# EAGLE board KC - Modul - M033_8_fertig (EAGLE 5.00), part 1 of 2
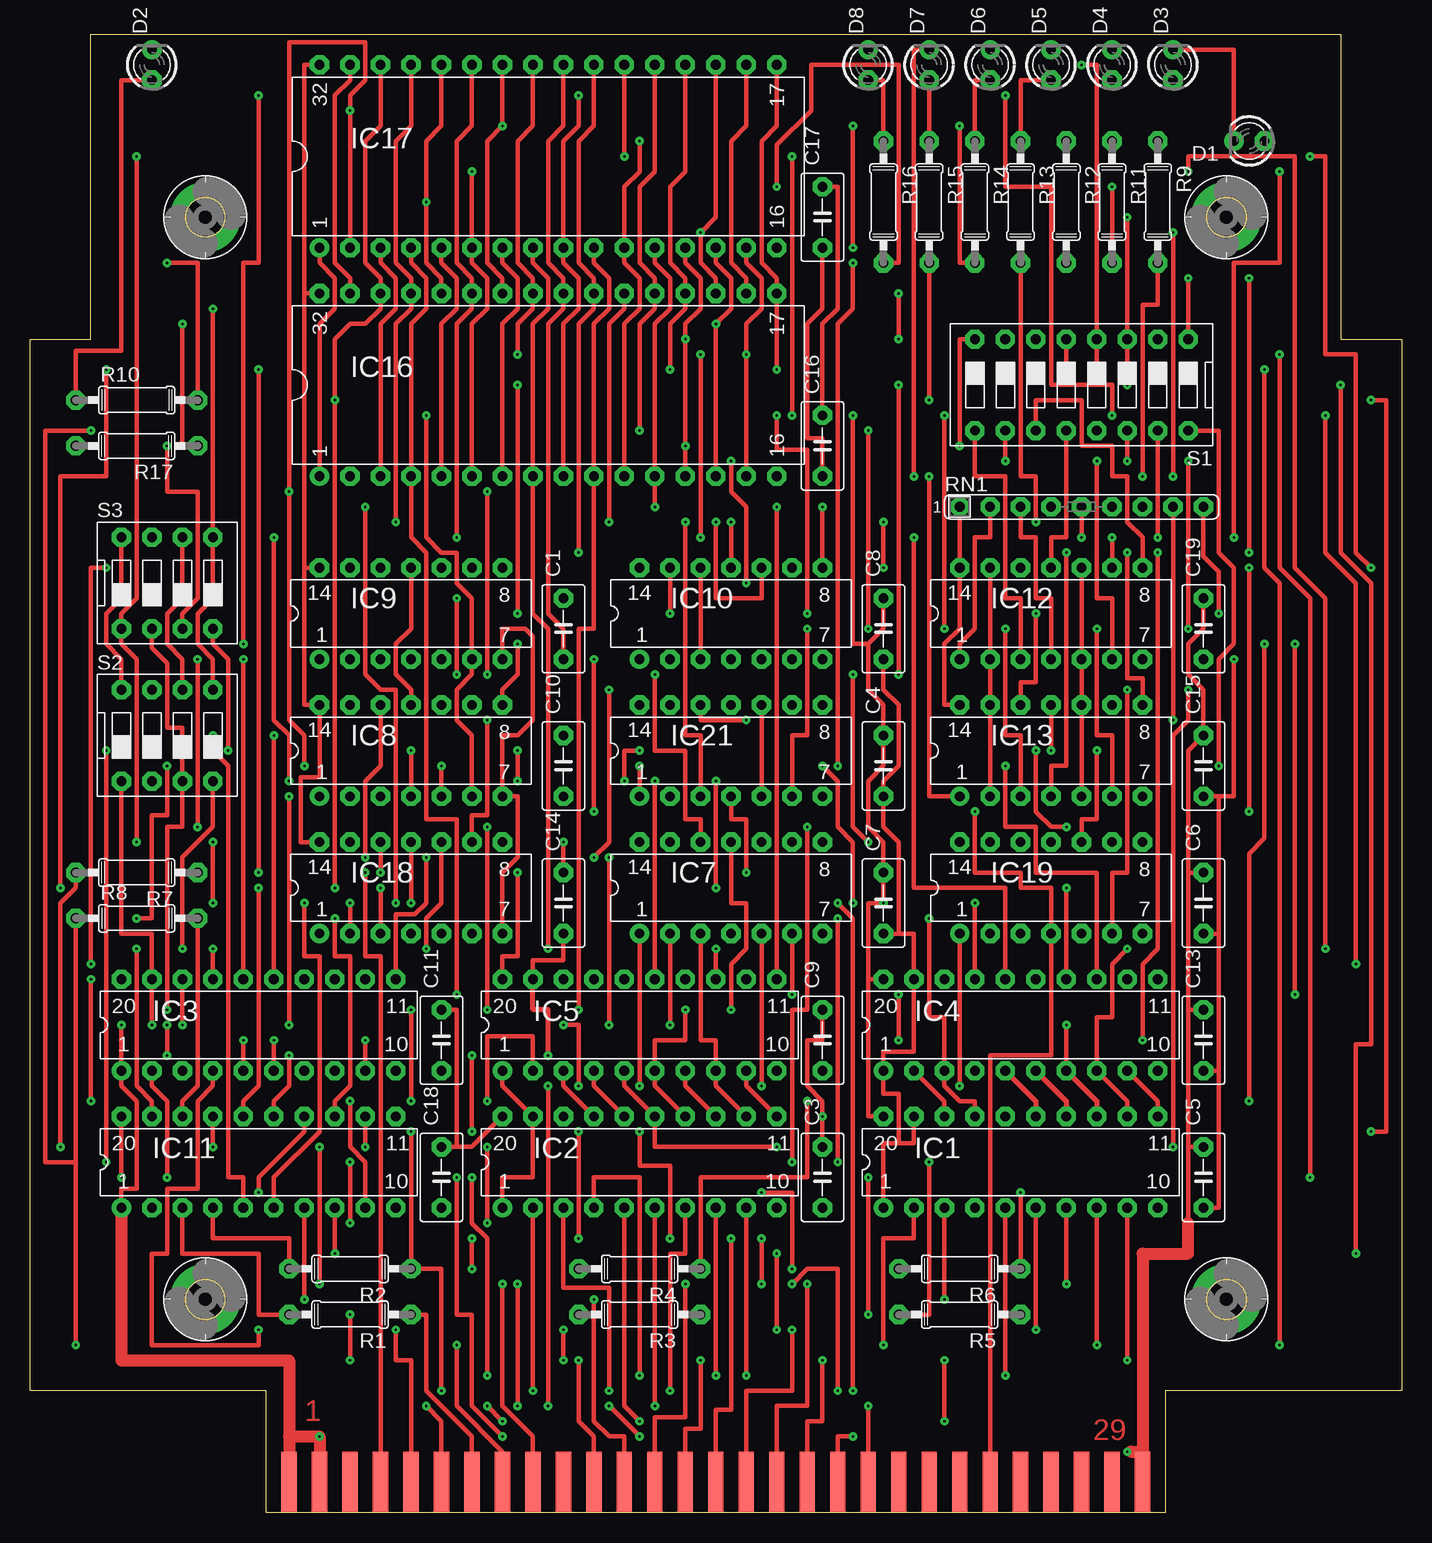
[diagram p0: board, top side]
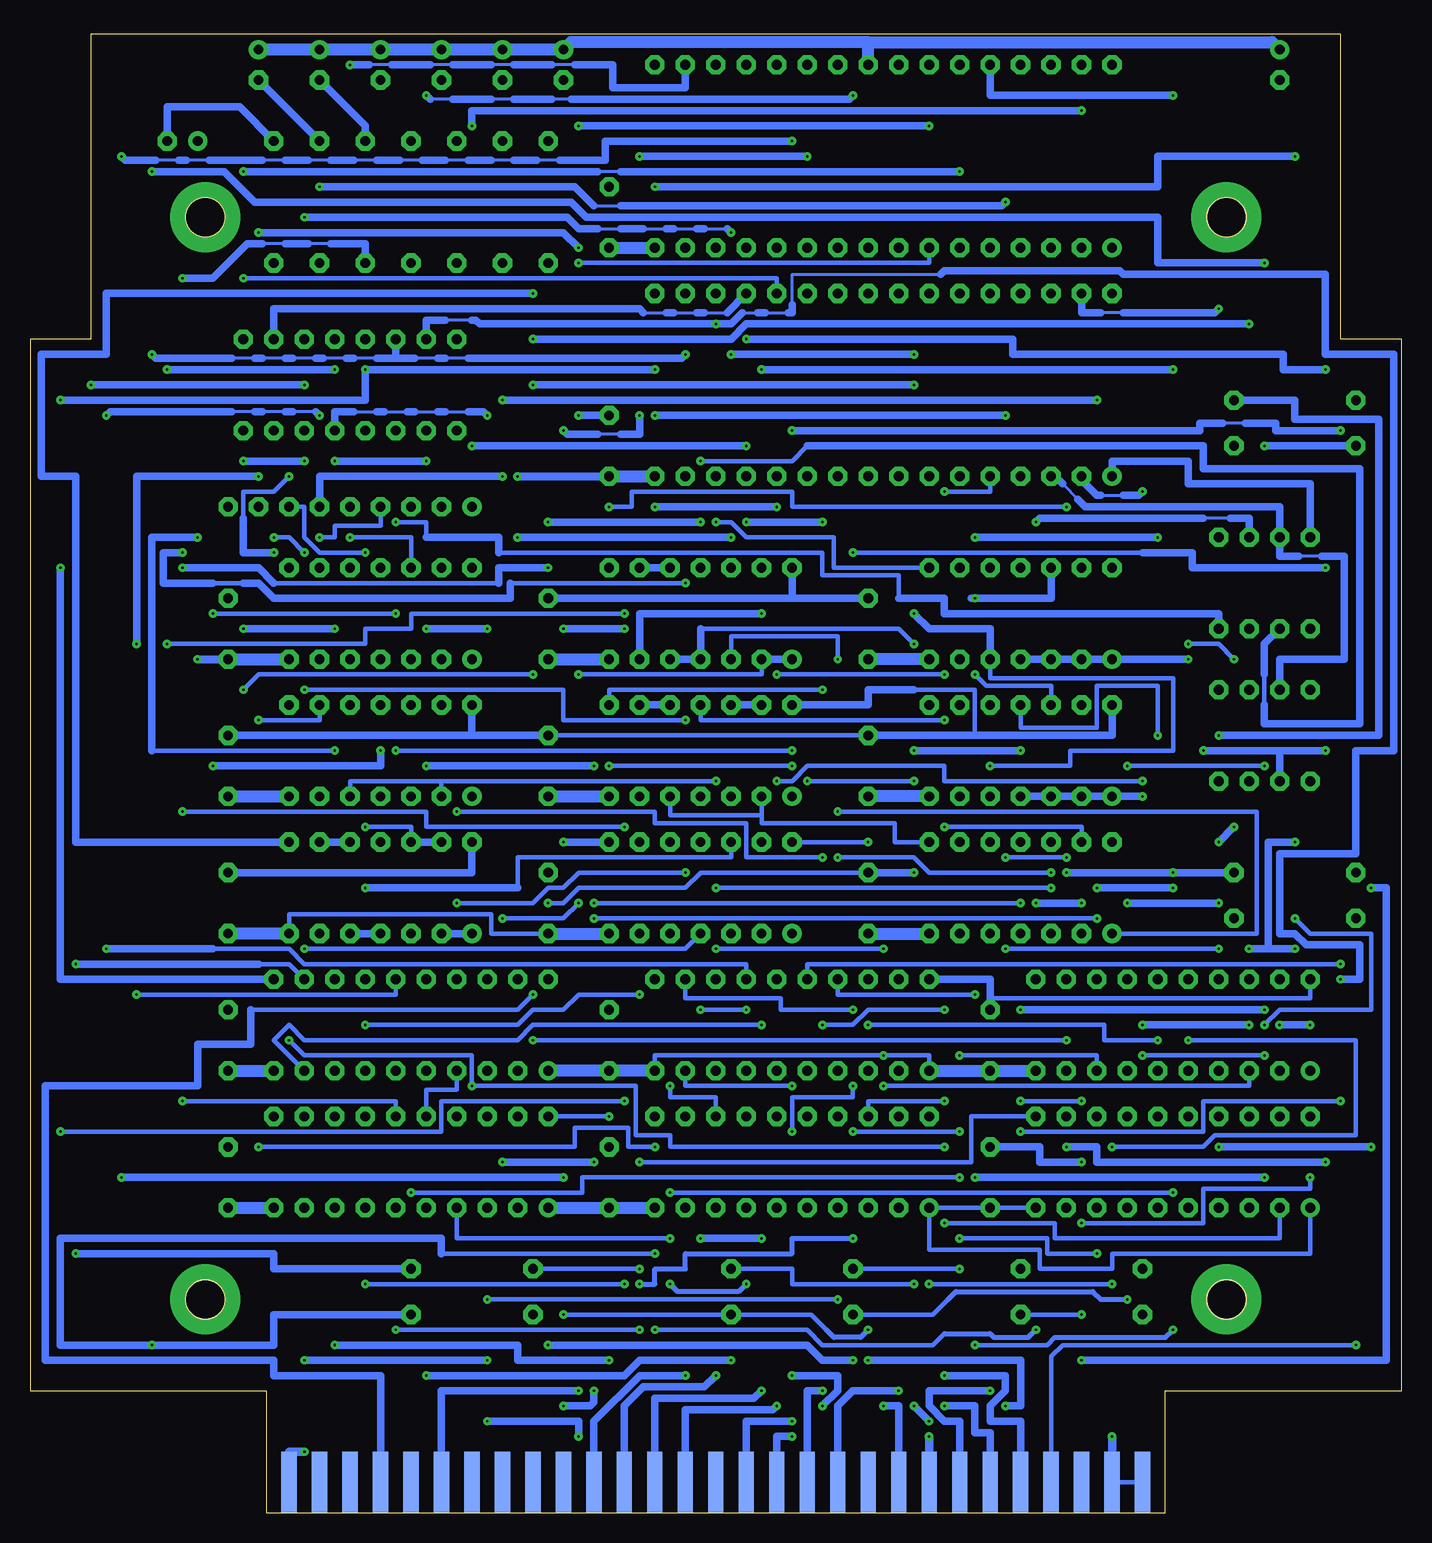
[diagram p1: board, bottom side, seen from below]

Size 114.3 x 123.19 mm. Coordinates in mm from the lower left corner, seen from the top.
Outline: 114.3,97.79 114.3,10.16 94.62,10.16 94.62,0 19.69,0 19.69,10.16 0,10.16 0,97.79 5.08,97.79 5.08,123.19 109.22,123.19 109.22,97.79 114.3,97.79
Copper layers (1*16): Top 0.035mm / dielectric 1.5mm / Bottom 0.035mm
Design rules "default": minimum track width 10mil, minimum drill 24mil, track to track 8mil, track to pad 8mil, pad to pad 8mil, via to via 8mil, smd to smd 8mil, copper to edge 40mil, drill to drill 8mil, minimum pad ring 10mil, minimum via ring 8mil, stop-mask expansion 4mil, vias tented up to drill 0mil, thermal gap 10mil
Holes 3.2 mm at 14.61,107.95 99.69,107.95 99.69,17.78 14.61,17.78

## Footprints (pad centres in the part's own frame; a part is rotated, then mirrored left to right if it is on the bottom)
C5B3,5 = drill 0.813 pad 1.6 octagon: 1 -2.54,0; 2 2.54,0
LED3 = drill 0.813 pad 1.6 octagon: A -1.27,0 | drill 0.813 pad 1.6 round: K 1.27,0
DIL20 = drill 0.813 pad 1.6 round: 1 -11.43,-3.81 | drill 0.813 pad 1.6 octagon: 2 -8.89,-3.81; 3 -6.35,-3.81; 4 -3.81,-3.81; 5 -1.27,-3.81; 6 1.27,-3.81; 7 3.81,-3.81; 8 6.35,-3.81; 9 8.89,-3.81; 10 11.43,-3.81; 11 11.43,3.81; 12 8.89,3.81; 13 6.35,3.81; 14 3.81,3.81; 15 1.27,3.81; 16 -1.27,3.81; 17 -3.81,3.81; 18 -6.35,3.81; 19 -8.89,3.81; 20 -11.43,3.81
DIL14 = drill 0.813 pad 1.6 round: 1 -7.62,-3.81 | drill 0.813 pad 1.6 octagon: 2 -5.08,-3.81; 3 -2.54,-3.81; 4 0,-3.81; 5 2.54,-3.81; 6 5.08,-3.81; 7 7.62,-3.81; 8 7.62,3.81; 9 5.08,3.81; 10 2.54,3.81; 11 0,3.81; 12 -2.54,3.81; 13 -5.08,3.81; 14 -7.62,3.81
DIL32 = drill 0.813 pad 1.6 round: 1 -19.05,-7.62 | drill 0.813 pad 1.6 octagon: 2 -16.51,-7.62; 3 -13.97,-7.62; 4 -11.43,-7.62; 5 -8.89,-7.62; 6 -6.35,-7.62; 7 -3.81,-7.62; 8 -1.27,-7.62; 9 1.27,-7.62; 10 3.81,-7.62; 11 6.35,-7.62; 12 8.89,-7.62; 13 11.43,-7.62; 14 13.97,-7.62; 15 16.51,-7.62; 16 19.05,-7.62; 17 19.05,7.62; 18 16.51,7.62; 19 13.97,7.62; 20 11.43,7.62; 21 8.89,7.62; 22 6.35,7.62; 23 3.81,7.62; 24 1.27,7.62; 25 -1.27,7.62; 26 -3.81,7.62; 27 -6.35,7.62; 28 -8.89,7.62; 29 -11.43,7.62; 30 -13.97,7.62; 31 -16.51,7.62; 32 -19.05,7.62
BO3,0-P = drill 3.023 pad 5.842 round: B3,0 0,0
SMD2 = smd 1.27 x 2.54: 1 0,0
0207/10 = drill 0.813 pad 1.6 octagon: 1 -5.08,0; 2 5.08,0
SIL9 = drill 0.813 pad 1.6 round: 1 -10.16,0 | drill 0.813 pad 1.6 octagon: 2 -7.62,0; 3 -5.08,0; 4 -2.54,0; 5 0,0; 6 2.54,0; 7 5.08,0; 8 7.62,0; 9 10.16,0
DS-08 = drill 0.813 pad 1.6 octagon: 1 -8.89,-3.81; 2 -6.35,-3.81; 3 -3.81,-3.81; 4 -1.27,-3.81; 5 1.27,-3.81; 6 3.81,-3.81; 7 6.35,-3.81; 8 8.89,-3.81; 9 8.89,3.81; 10 6.35,3.81; 11 3.81,3.81; 12 1.27,3.81; 13 -1.27,3.81; 14 -3.81,3.81; 15 -6.35,3.81; 16 -8.89,3.81
DS-04 = drill 0.813 pad 1.6 octagon: 1 -3.81,-3.81; 2 -1.27,-3.81; 3 1.27,-3.81; 4 3.81,-3.81; 5 3.81,3.81; 6 1.27,3.81; 7 -1.27,3.81; 8 -3.81,3.81

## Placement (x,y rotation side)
C1  C5B3,5  [C5B3,5]  44.45,73.66 90 top
C3  C5B3,5  [C5B3,5]  66.04,27.94 90 top
C4  C5B3,5  [C5B3,5]  71.12,62.23 90 top
C5  C5B3,5  [C5B3,5]  97.79,27.94 90 top
C6  C5B3,5  [C5B3,5]  97.79,50.8 90 top
C7  C5B3,5  [C5B3,5]  71.12,50.8 90 top
C8  C5B3,5  [C5B3,5]  71.12,73.66 90 top
C9  C5B3,5  [C5B3,5]  66.04,39.37 90 top
C10  C5B3,5  [C5B3,5]  44.45,62.23 90 top
C11  C5B3,5  [C5B3,5]  34.29,39.37 90 top
C13  C5B3,5  [C5B3,5]  97.79,39.37 90 top
C14  C5B3,5  [C5B3,5]  44.45,50.8 90 top
C15  C5B3,5  [C5B3,5]  97.79,62.23 90 top
C16  C5B3,5  [C5B3,5]  66.04,88.9 90 top
C17  C5B3,5  [C5B3,5]  66.04,107.95 90 top
C18  C5B3,5  [C5B3,5]  34.29,27.94 90 top
C19  C5B3,5  [C5B3,5]  97.79,73.66 90 top
D1  [LED3]  101.6,114.3 180 top
D2  [LED3]  10.16,120.65 90 top
D3  [LED3]  95.25,120.65 90 top
D4  [LED3]  90.17,120.65 90 top
D5  [LED3]  85.09,120.65 90 top
D6  [LED3]  80.01,120.65 90 top
D7  [LED3]  74.93,120.65 90 top
D8  [LED3]  69.85,120.65 90 top
IC1  74540  [DIL20]  82.55,29.21 0 top
IC2  74540  [DIL20]  50.8,29.21 0 top
IC3  74540  [DIL20]  19.05,40.64 0 top
IC4  74540  [DIL20]  82.55,40.64 0 top
IC5  74540  [DIL20]  50.8,40.64 0 top
IC7  7430  [DIL14]  58.42,52.07 0 top
IC8  7430  [DIL14]  31.75,63.5 0 top
IC9  7430  [DIL14]  31.75,74.93 0 top
IC10  7400  [DIL14]  58.42,74.93 0 top
IC11  74374  [DIL20]  19.05,29.21 0 top
IC12  7403  [DIL14]  85.09,74.93 0 top
IC13  7403  [DIL14]  85.09,63.5 0 top
IC16  628128P  [DIL32]  43.18,93.98 0 top
IC17  628128P  [DIL32]  43.18,113.03 0 top
IC18  7408  [DIL14]  31.75,52.07 0 top
IC19  7420  [DIL14]  85.09,52.07 0 top
IC21  7400  [DIL14]  58.42,63.5 0 top
PAD1  BO3,0P  [BO3,0-P]  99.69,17.78 0 top
PAD2  BO3,0P  [BO3,0-P]  14.61,17.78 0 top
PAD3  BO3,0P  [BO3,0-P]  99.69,107.95 0 top
PAD4  BO3,0P  [BO3,0-P]  14.61,107.95 0 top
PAD5  SMD2  [SMD2]  21.59,1.27 0 top
PAD6  SMD2  [SMD2]  24.13,1.27 0 top
PAD7  SMD2  [SMD2]  26.67,1.27 0 top
PAD8  SMD2  [SMD2]  29.21,1.27 0 top
PAD9  SMD2  [SMD2]  31.75,1.27 0 top
PAD10  SMD2  [SMD2]  34.29,1.27 0 top
PAD11  SMD2  [SMD2]  36.83,1.27 0 top
PAD12  SMD2  [SMD2]  39.37,1.27 0 top
PAD13  SMD2  [SMD2]  41.91,1.27 0 top
PAD14  SMD2  [SMD2]  44.45,1.27 0 top
PAD15  SMD2  [SMD2]  46.99,1.27 0 top
PAD16  SMD2  [SMD2]  49.53,1.27 0 top
PAD17  SMD2  [SMD2]  52.07,1.27 0 top
PAD18  SMD2  [SMD2]  54.61,1.27 0 top
PAD19  SMD2  [SMD2]  57.15,1.27 0 top
PAD20  SMD2  [SMD2]  59.69,1.27 0 top
PAD21  SMD2  [SMD2]  62.23,1.27 0 top
PAD22  SMD2  [SMD2]  64.77,1.27 0 top
PAD23  SMD2  [SMD2]  67.31,1.27 0 top
PAD24  SMD2  [SMD2]  69.85,1.27 0 top
PAD25  SMD2  [SMD2]  72.39,1.27 0 top
PAD26  SMD2  [SMD2]  74.93,1.27 0 top
PAD27  SMD2  [SMD2]  77.47,1.27 0 top
PAD28  SMD2  [SMD2]  80.01,1.27 0 top
PAD29  SMD2  [SMD2]  82.55,1.27 0 top
PAD30  SMD2  [SMD2]  85.09,1.27 0 top
PAD31  SMD2  [SMD2]  87.63,1.27 0 top
PAD32  SMD2  [SMD2]  90.17,1.27 0 top
PAD33  SMD2  [SMD2]  92.71,1.27 0 top
PAD34  SMD2  [SMD2]  21.59,3.81 0 top
PAD35  SMD2  [SMD2]  24.13,3.81 0 top
PAD36  SMD2  [SMD2]  26.67,3.81 0 top
PAD37  SMD2  [SMD2]  29.21,3.81 0 top
PAD38  SMD2  [SMD2]  31.75,3.81 0 top
PAD39  SMD2  [SMD2]  34.29,3.81 0 top
PAD40  SMD2  [SMD2]  36.83,3.81 0 top
PAD41  SMD2  [SMD2]  39.37,3.81 0 top
PAD42  SMD2  [SMD2]  41.91,3.81 0 top
PAD43  SMD2  [SMD2]  44.45,3.81 0 top
PAD44  SMD2  [SMD2]  46.99,3.81 0 top
PAD45  SMD2  [SMD2]  49.53,3.81 0 top
PAD46  SMD2  [SMD2]  52.07,3.81 0 top
PAD47  SMD2  [SMD2]  54.61,3.81 0 top
PAD48  SMD2  [SMD2]  57.15,3.81 0 top
PAD49  SMD2  [SMD2]  59.69,3.81 0 top
PAD50  SMD2  [SMD2]  62.23,3.81 0 top
PAD51  SMD2  [SMD2]  64.77,3.81 0 top
PAD52  SMD2  [SMD2]  67.31,3.81 0 top
PAD53  SMD2  [SMD2]  69.85,3.81 0 top
PAD54  SMD2  [SMD2]  72.39,3.81 0 top
PAD55  SMD2  [SMD2]  74.93,3.81 0 top
PAD56  SMD2  [SMD2]  77.47,3.81 0 top
PAD57  SMD2  [SMD2]  80.01,3.81 0 top
PAD58  SMD2  [SMD2]  82.55,3.81 0 top
PAD59  SMD2  [SMD2]  85.09,3.81 0 top
PAD60  SMD2  [SMD2]  87.63,3.81 0 top
PAD61  SMD2  [SMD2]  90.17,3.81 0 top
PAD62  SMD2  [SMD2]  92.71,3.81 0 top
PAD63  SMD2  [SMD2]  21.59,1.27 0 bottom
PAD64  SMD2  [SMD2]  24.13,1.27 0 bottom
PAD65  SMD2  [SMD2]  26.67,1.27 0 bottom
PAD66  SMD2  [SMD2]  29.21,1.27 0 bottom
PAD67  SMD2  [SMD2]  31.75,1.27 0 bottom
PAD68  SMD2  [SMD2]  34.29,1.27 0 bottom
PAD69  SMD2  [SMD2]  36.83,1.27 0 bottom
PAD70  SMD2  [SMD2]  39.37,1.27 0 bottom
PAD71  SMD2  [SMD2]  41.91,1.27 0 bottom
PAD72  SMD2  [SMD2]  44.45,1.27 0 bottom
PAD73  SMD2  [SMD2]  46.99,1.27 0 bottom
PAD74  SMD2  [SMD2]  49.53,1.27 0 bottom
PAD75  SMD2  [SMD2]  52.07,1.27 0 bottom
PAD76  SMD2  [SMD2]  54.61,1.27 0 bottom
PAD77  SMD2  [SMD2]  57.15,1.27 0 bottom
PAD78  SMD2  [SMD2]  59.69,1.27 0 bottom
PAD79  SMD2  [SMD2]  62.23,1.27 0 bottom
PAD80  SMD2  [SMD2]  64.77,1.27 0 bottom
PAD81  SMD2  [SMD2]  67.31,1.27 0 bottom
PAD82  SMD2  [SMD2]  69.85,1.27 0 bottom
PAD83  SMD2  [SMD2]  72.39,1.27 0 bottom
PAD84  SMD2  [SMD2]  74.93,1.27 0 bottom
PAD85  SMD2  [SMD2]  77.47,1.27 0 bottom
PAD86  SMD2  [SMD2]  80.01,1.27 0 bottom
PAD87  SMD2  [SMD2]  82.55,1.27 0 bottom
PAD88  SMD2  [SMD2]  85.09,1.27 0 bottom
PAD89  SMD2  [SMD2]  87.63,1.27 0 bottom
PAD90  SMD2  [SMD2]  90.17,1.27 0 bottom
PAD91  SMD2  [SMD2]  92.71,1.27 0 bottom
PAD92  SMD2  [SMD2]  21.59,3.81 0 bottom
PAD93  SMD2  [SMD2]  24.13,3.81 0 bottom
PAD94  SMD2  [SMD2]  26.67,3.81 0 bottom
PAD95  SMD2  [SMD2]  29.21,3.81 0 bottom
PAD96  SMD2  [SMD2]  31.75,3.81 0 bottom
PAD97  SMD2  [SMD2]  34.29,3.81 0 bottom
PAD98  SMD2  [SMD2]  36.83,3.81 0 bottom
PAD99  SMD2  [SMD2]  39.37,3.81 0 bottom
PAD100  SMD2  [SMD2]  41.91,3.81 0 bottom
PAD101  SMD2  [SMD2]  44.45,3.81 0 bottom
PAD102  SMD2  [SMD2]  46.99,3.81 0 bottom
PAD103  SMD2  [SMD2]  49.53,3.81 0 bottom
PAD104  SMD2  [SMD2]  52.07,3.81 0 bottom
PAD105  SMD2  [SMD2]  54.61,3.81 0 bottom
PAD106  SMD2  [SMD2]  57.15,3.81 0 bottom
PAD107  SMD2  [SMD2]  59.69,3.81 0 bottom
PAD108  SMD2  [SMD2]  62.23,3.81 0 bottom
PAD109  SMD2  [SMD2]  64.77,3.81 0 bottom
PAD110  SMD2  [SMD2]  67.31,3.81 0 bottom
PAD111  SMD2  [SMD2]  69.85,3.81 0 bottom
PAD112  SMD2  [SMD2]  72.39,3.81 0 bottom
PAD113  SMD2  [SMD2]  74.93,3.81 0 bottom
PAD114  SMD2  [SMD2]  77.47,3.81 0 bottom
PAD115  SMD2  [SMD2]  80.01,3.81 0 bottom
PAD116  SMD2  [SMD2]  82.55,3.81 0 bottom
PAD117  SMD2  [SMD2]  85.09,3.81 0 bottom
PAD118  SMD2  [SMD2]  87.63,3.81 0 bottom
PAD119  SMD2  [SMD2]  90.17,3.81 0 bottom
PAD120  SMD2  [SMD2]  92.71,3.81 0 bottom
R1  100 Ohm  [0207/10]  26.67,16.51 180 top
R2  100 Ohm  [0207/10]  26.67,20.32 180 top
R3  100 Ohm  [0207/10]  50.8,16.51 180 top
R4  100 Ohm  [0207/10]  50.8,20.32 180 top
R5  100 Ohm  [0207/10]  77.47,16.51 180 top
R6  100 Ohm  [0207/10]  77.47,20.32 180 top
R7  100 Ohm  [0207/10]  8.89,53.34 180 top
R8  100 Ohm  [0207/10]  8.89,49.53 0 top
R9  3,9 kOhm  [0207/10]  93.98,109.22 270 top
R10  330 Ohm  [0207/10]  8.89,92.71 0 top
R11  330 Ohm  [0207/10]  90.17,109.22 270 top
R12  330 Ohm  [0207/10]  86.36,109.22 270 top
R13  330 Ohm  [0207/10]  82.55,109.22 270 top
R14  330 Ohm  [0207/10]  78.74,109.22 270 top
R15  330 Ohm  [0207/10]  74.93,109.22 270 top
R16  330 Ohm  [0207/10]  71.12,109.22 270 top
R17  4,7 Ohm  [0207/10]  8.89,88.9 180 top
RN1  4,7 kOhm  [SIL9]  87.63,83.82 0 top
S1  DS08  [DS-08]  87.63,93.98 180 top
S2  EPROM  [DS-04]  11.43,64.77 0 top
S3  SRAM  [DS-04]  11.43,77.47 0 top

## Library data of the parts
C1 C3-C11 C13-C19 = CAP
D1-D8 = LED
IC1-IC5 IC7-IC13 IC18 IC19 IC21 = 74XX
IC16 IC17 = MEMHITCH
PAD1-PAD4 = HOLES
PAD5-PAD120 = WIREPAD
R1-R17 = R
RN1 = R-SIL
S1-S3 = DILSWTCH

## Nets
80H: IC10.3 IC10.12 IC18.1
/A0: IC2.11 IC5.9 IC7.1
/A1: IC1.11 IC4.9 IC7.2
/A2: IC2.12 IC5.8 IC7.3
/A3: IC1.12 IC4.8 IC7.4
/A4: IC2.13 IC5.7 IC7.5
/A5: IC1.13 IC4.7 IC7.6
/A6: IC2.14 IC5.6 IC7.11
/A8: IC2.15 IC5.5 IC8.5 IC9.5
/A9: IC1.15 IC4.5 IC8.6 IC9.6
/A10: IC2.16 IC5.4
/A11: IC1.16 IC4.4
/A12: IC2.17 IC5.3
/A13: IC1.17 IC4.3 IC21.1
/A14: IC2.18 IC5.2
/A15: IC1.18 IC4.2
A0: IC5.11 IC16.12 IC17.12
A1: IC4.11 IC16.11 IC17.11
A2: IC5.12 IC16.10 IC17.10
A3: IC4.12 IC16.9 IC17.9
A4: IC5.13 IC16.8 IC17.8
A5: IC4.13 IC16.7 IC17.7
A6: IC5.14 IC16.6 IC17.6
A7: IC4.14 IC7.12 IC16.5 IC17.5
A8: IC5.15 IC16.27 IC17.27
A9: IC4.15 IC16.26 IC17.26
A10: IC5.16 IC16.23 IC17.23
A11: IC4.16 IC16.25 IC17.25
A12: IC5.17 IC16.4 IC17.4
A13: IC4.17 IC21.4
A14: IC5.18
A15: IC4.18
AB0: IC2.9 PAD81.1 PAD110.1
AB1: IC1.9 PAD23.1 PAD52.1
AB2: IC2.8 PAD80.1 PAD109.1
AB3: IC1.8 PAD22.1 PAD51.1
AB4: IC2.7 PAD79.1 PAD108.1
AB5: IC1.7 PAD21.1 PAD50.1
AB6: IC2.6 PAD78.1 PAD107.1
AB7: IC1.6 PAD20.1 PAD49.1
AB8: IC2.5 PAD76.1 PAD105.1
AB9: IC1.5 PAD18.1 PAD47.1
AB10: IC2.4 PAD75.1 PAD104.1
AB11: IC1.4 PAD17.1 PAD46.1
AB12: IC2.3 PAD74.1 PAD103.1
AB13: IC1.3 PAD16.1 PAD45.1
AB14: IC2.2 PAD73.1 PAD102.1
AB15: IC1.2 PAD15.1 PAD44.1
B_03A: PAD65.1 PAD94.1
B_03B: PAD7.1 PAD36.1
B_08A: IC3.2 PAD70.1 PAD99.1
B_08B: IC3.4 PAD12.1 PAD41.1
B_09A: IC3.3 PAD71.1 PAD100.1
B_09B: IC3.5 PAD13.1 PAD42.1
B_10A: PAD72.1 PAD101.1
B_15A: PAD77.1 PAD106.1
B_15B: IC3.6 PAD19.1 PAD48.1
B_20A: PAD82.1 PAD111.1
B_20B: IC3.8 PAD24.1 PAD53.1
B_21A: PAD83.1 PAD112.1
B_21B: PAD25.1 PAD54.1
B_22A: PAD84.1 PAD113.1
B_22B: PAD26.1 PAD55.1
B_23A: PAD85.1 PAD114.1
B_23B: PAD27.1 PAD56.1
B_25A: PAD87.1 PAD116.1
B_25B: PAD29.1 PAD58.1
B_26A: IC3.9 PAD88.1 PAD117.1
B_26B: PAD30.1 PAD59.1
B_27A: PAD89.1 PAD118.1
B_27B: PAD31.1 PAD60.1
B_28A: PAD90.1 PAD119.1
B_28B: PAD32.1 PAD61.1
BUSRQ: IC3.12
CSRAM1: IC16.22 IC21.3
CSRAM2: IC17.22 IC21.6
D0: IC16.13 IC17.13 PAD11.1 PAD40.1 R1.1 S1.8
D1: IC16.14 IC17.14 PAD69.1 PAD98.1 R2.1
D2: IC16.15 IC17.15 PAD10.1 PAD39.1 R3.1 S1.6
D3: IC16.17 IC17.17 PAD68.1 PAD97.1 R4.1 S1.5
D4: IC16.18 IC17.18 PAD9.1 PAD38.1 R5.1 S1.4
D5: IC16.19 IC17.19 PAD67.1 PAD96.1 R6.1 S1.3
D6: IC16.20 IC17.20 PAD8.1 PAD37.1 R7.1 S1.2
D7: IC16.21 IC17.21 PAD66.1 PAD95.1 R8.1 S1.1
GND: C1.1 C3.1 C4.1 C5.1 C6.1 C7.1 C8.1 C9.1 C10.1 C11.1 C13.1 C14.1 C15.1 C16.1 C17.1 C18.1 C19.1 D1.K D2.K D3.K D4.K D5.K D6.K D7.K D8.K IC1.1 IC1.10 IC1.19 IC2.1 IC2.10 IC2.19 IC3.1 IC3.10 IC3.19 IC4.1 IC4.10 IC4.19 IC5.1 IC5.10 IC5.19 IC7.7 IC8.7 IC9.7 IC10.7 IC11.1 IC11.10 IC12.7 IC13.7 IC16.16 IC16.24 IC17.16 IC17.24 IC18.7 IC19.7 IC21.7 PAD5.1 PAD6.1 PAD34.1 PAD35.1 PAD63.1 PAD64.1 PAD92.1 PAD93.1 S2.1
IC13: IC11.6 IC16.28 IC17.28 R11.2
IC16: IC11.15 IC16.2 IC17.2 R14.2
IC17: IC11.16 IC16.30 IC17.30 R15.2
IC_A_14: IC11.9 R12.2 S2.3 S3.2
IC_A_15: IC11.12 R13.2 S2.2 S3.4
IC_A_18: IC11.19 R16.2 S2.4 S3.1
IC_WE: R17.2 S3.3
IE_I_O: PAD14.1 PAD43.1
IORQ: IC3.15 IC8.11 IC9.11
LATCH: IC10.11 IC11.11
MAD: IC3.11 IC8.12 IC9.12
MEI: IC18.13 IC19.4 IC19.5 PAD28.1 PAD57.1
MEO: IC18.11 PAD86.1 PAD115.1
MKA: IC12.2 IC12.5 IC12.10 IC12.13 IC13.2 IC13.5 IC13.10 IC13.13 IC18.3
MREQ: IC3.17 IC18.10
N$1: IC7.8 IC10.1 IC10.2
N$2: IC12.1 RN1.2
N$3: IC12.4 RN1.3
N$4: IC12.9 RN1.4
N$5: IC12.12 RN1.5
N$6: IC13.1 RN1.6
N$7: IC13.4 RN1.7
N$8: IC13.9 RN1.8
N$9: IC13.12 RN1.9
N$10: IC10.8 IC18.2
N$11: IC18.8 IC21.2 IC21.5 IC21.9 IC21.10
N$12: IC11.4 R2.2
N$14: D8.A R16.1
N$15: IC8.8 IC10.4 IC10.5
N$16: IC18.12 IC21.8
N$17: IC12.3 S1.9
N$18: IC12.6 S1.10
N$19: IC12.8 S1.11
N$20: IC12.11 S1.12
N$21: IC13.3 S1.13
N$22: IC13.6 S1.14
N$23: IC13.8 S1.15
N$24: IC13.11 S1.16
N$25: IC19.8 R17.1
N$26: IC9.8 IC10.9 IC10.10
N$27: IC11.3 R1.2
N$28: IC11.5 IC19.9 IC19.10 R10.2
N$29: IC11.7 R3.2
N$30: IC11.8 R4.2
N$31: IC11.13 R5.2
N$32: IC11.14 R6.2
N$33: IC11.17 R7.2
N$34: IC11.18 R8.2
N$35: IC18.9 IC21.11
N$36: D7.A R15.1
N$37: IC10.6 IC10.13
N$41: D6.A R14.1
N$42: D5.A R13.1
N$45: IC11.2 IC19.1 IC19.2 R9.2
N$46: D1.A R9.1
N$48: D2.A R10.1
PIN1: IC16.1 IC17.1 S2.8 S3.8
PIN3: IC16.3 IC17.3 S2.7 S3.7
PIN29: IC16.29 IC17.29 S2.6 S3.6
PIN31: IC16.31 IC17.31 S2.5 S3.5
RD: IC3.16 IC9.1 IC9.2 IC9.3 IC9.4
RFSH: IC3.14
S$1: IC1.14 IC4.6
S$2: D4.A R12.1
S$3: D3.A R11.1
S$5: S1.7
VCC: C1.2 C3.2 C4.2 C5.2 C6.2 C7.2 C8.2 C9.2 C10.2 C11.2 C13.2 C14.2 C15.2 C16.2 C17.2 C18.2 C19.2 IC1.20 IC2.20 IC3.20 IC4.20 IC5.20 IC7.14 IC8.14 IC9.14 IC10.14 IC11.20 IC12.14 IC13.14 IC16.32 IC17.32 IC18.14 IC19.14 IC21.14 PAD33.1 PAD62.1 PAD91.1 PAD120.1 RN1.1
VON_374: IC19.6 IC21.12 IC21.13
WR: IC3.18 IC8.1 IC8.2 IC8.3 IC8.4 IC19.12 IC19.13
